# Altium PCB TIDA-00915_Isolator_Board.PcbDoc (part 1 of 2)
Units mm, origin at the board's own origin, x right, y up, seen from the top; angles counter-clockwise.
Board outline 80 x 46 mm, 4 copper layers (Top Layer, L2, L3, Bottom Layer), stack 0.8 mm thick; 132 components, 79 nets, 362 pads, 253 vias.
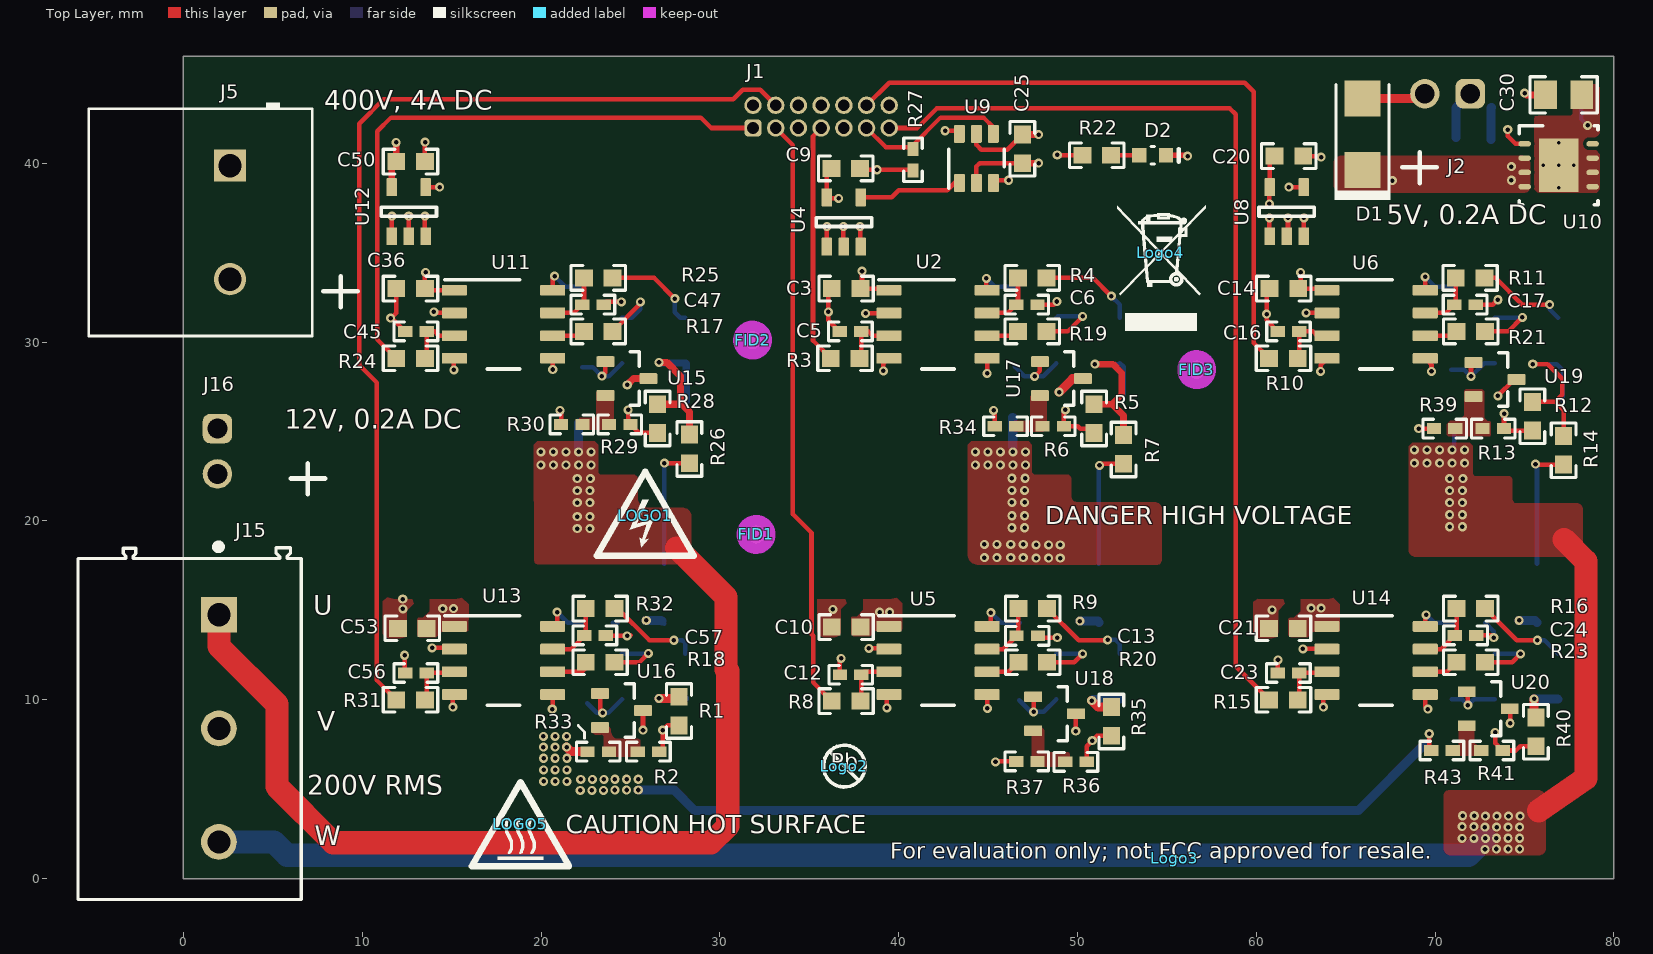
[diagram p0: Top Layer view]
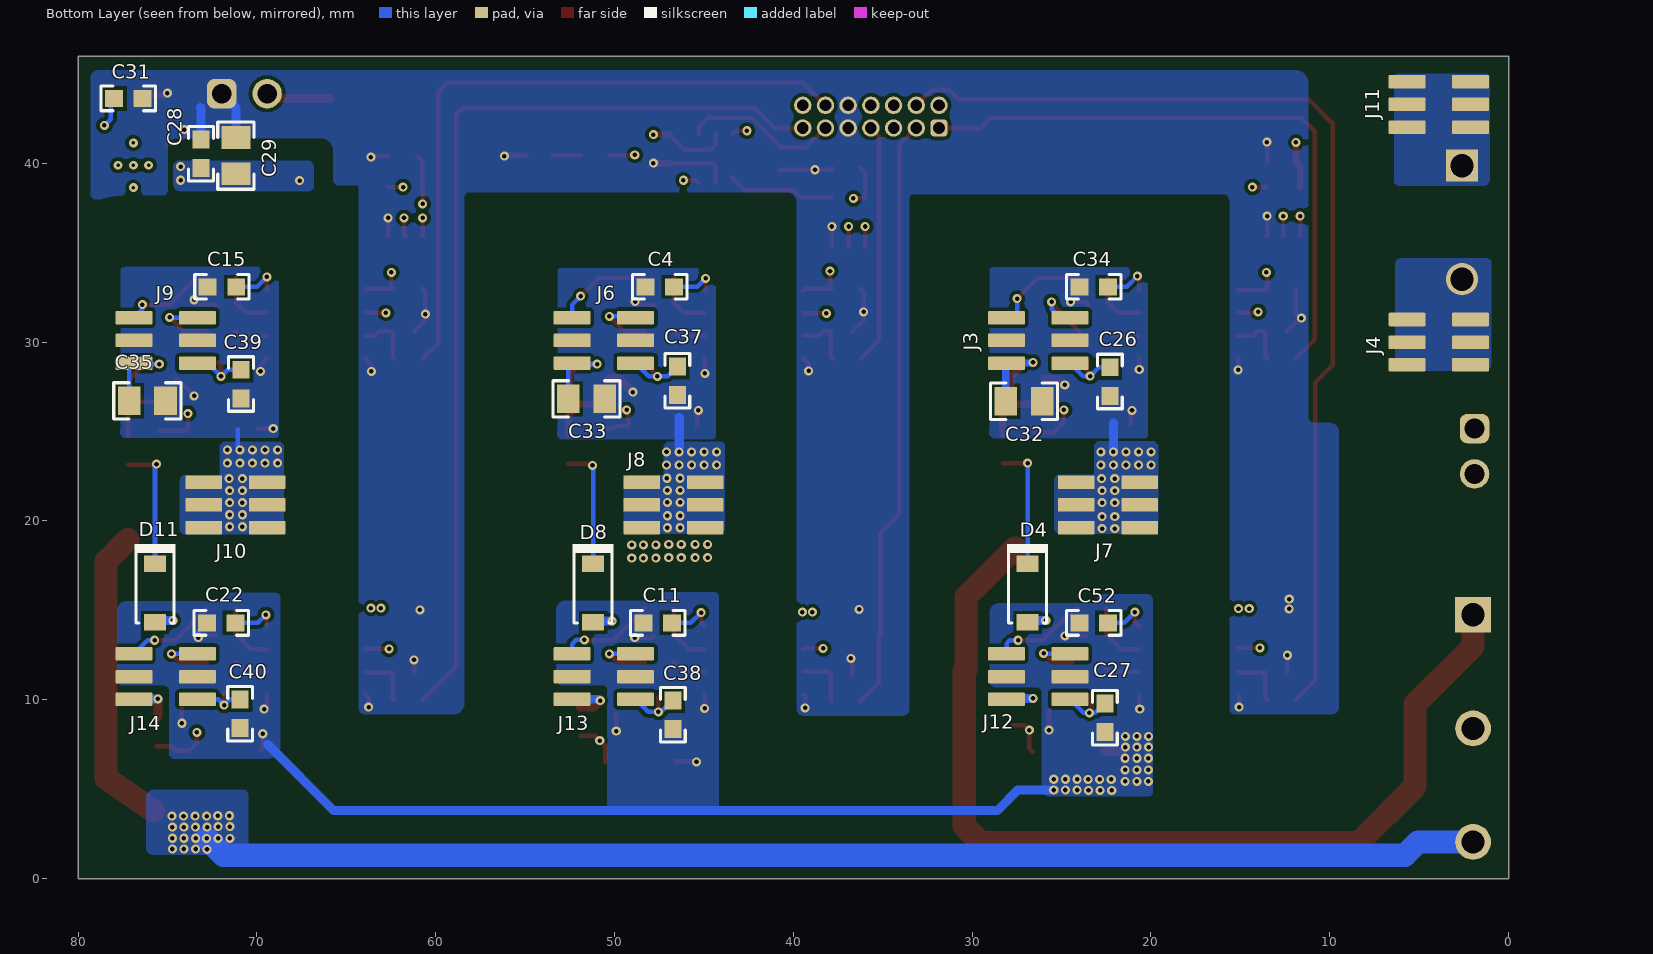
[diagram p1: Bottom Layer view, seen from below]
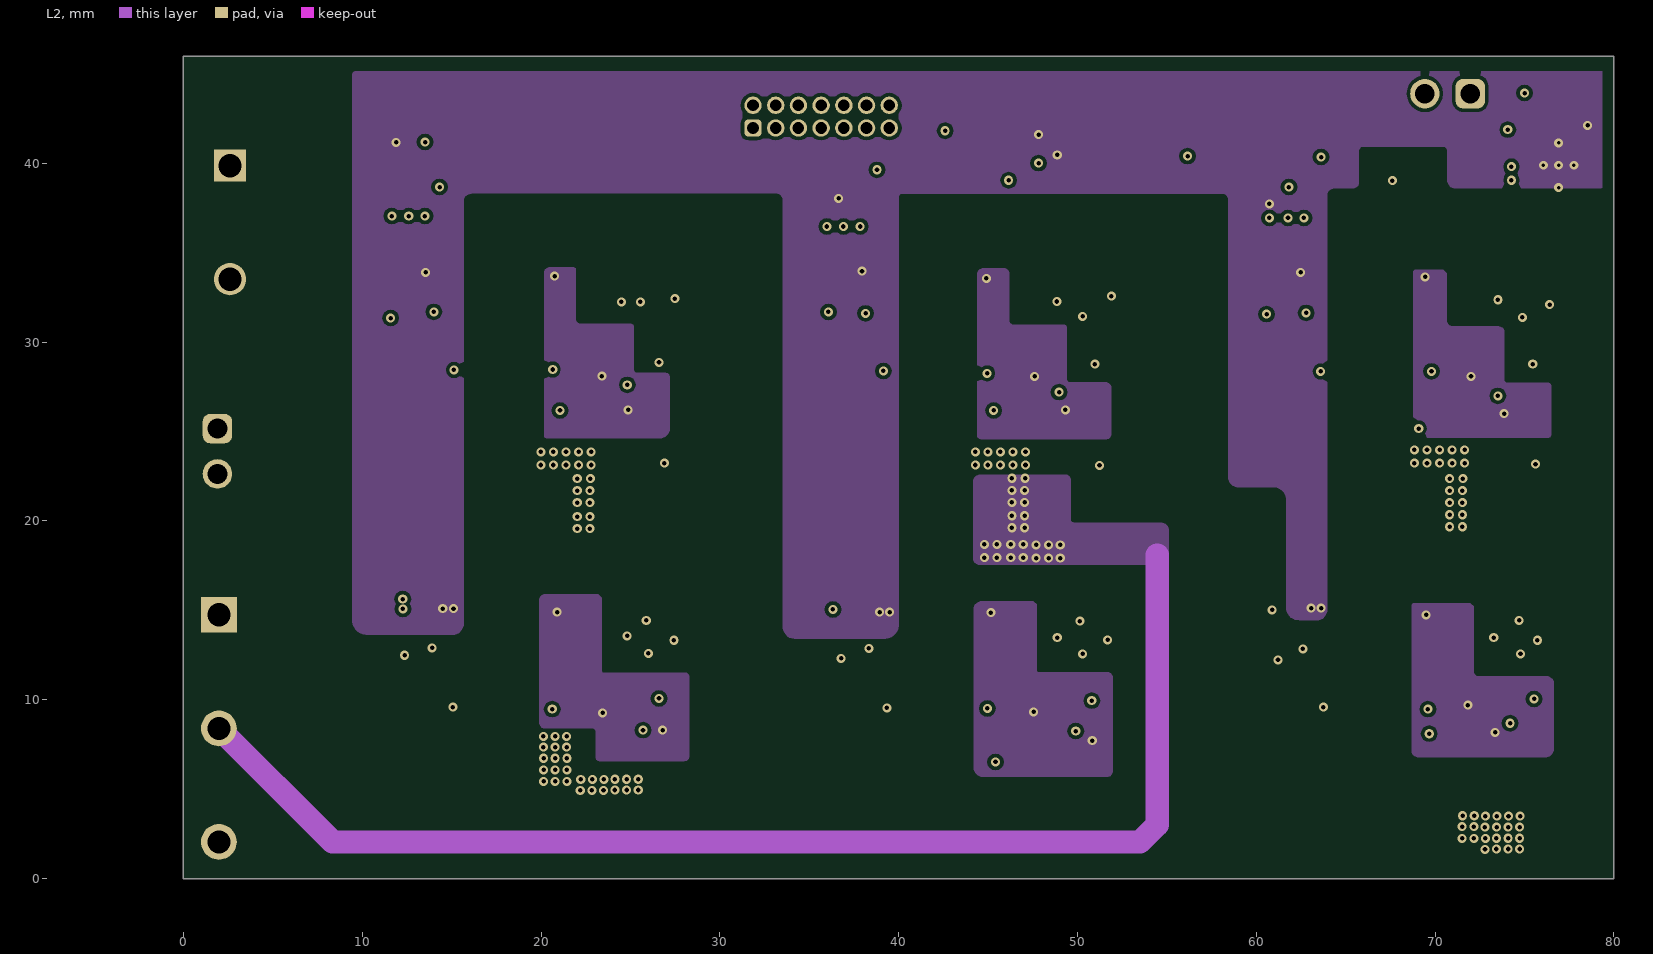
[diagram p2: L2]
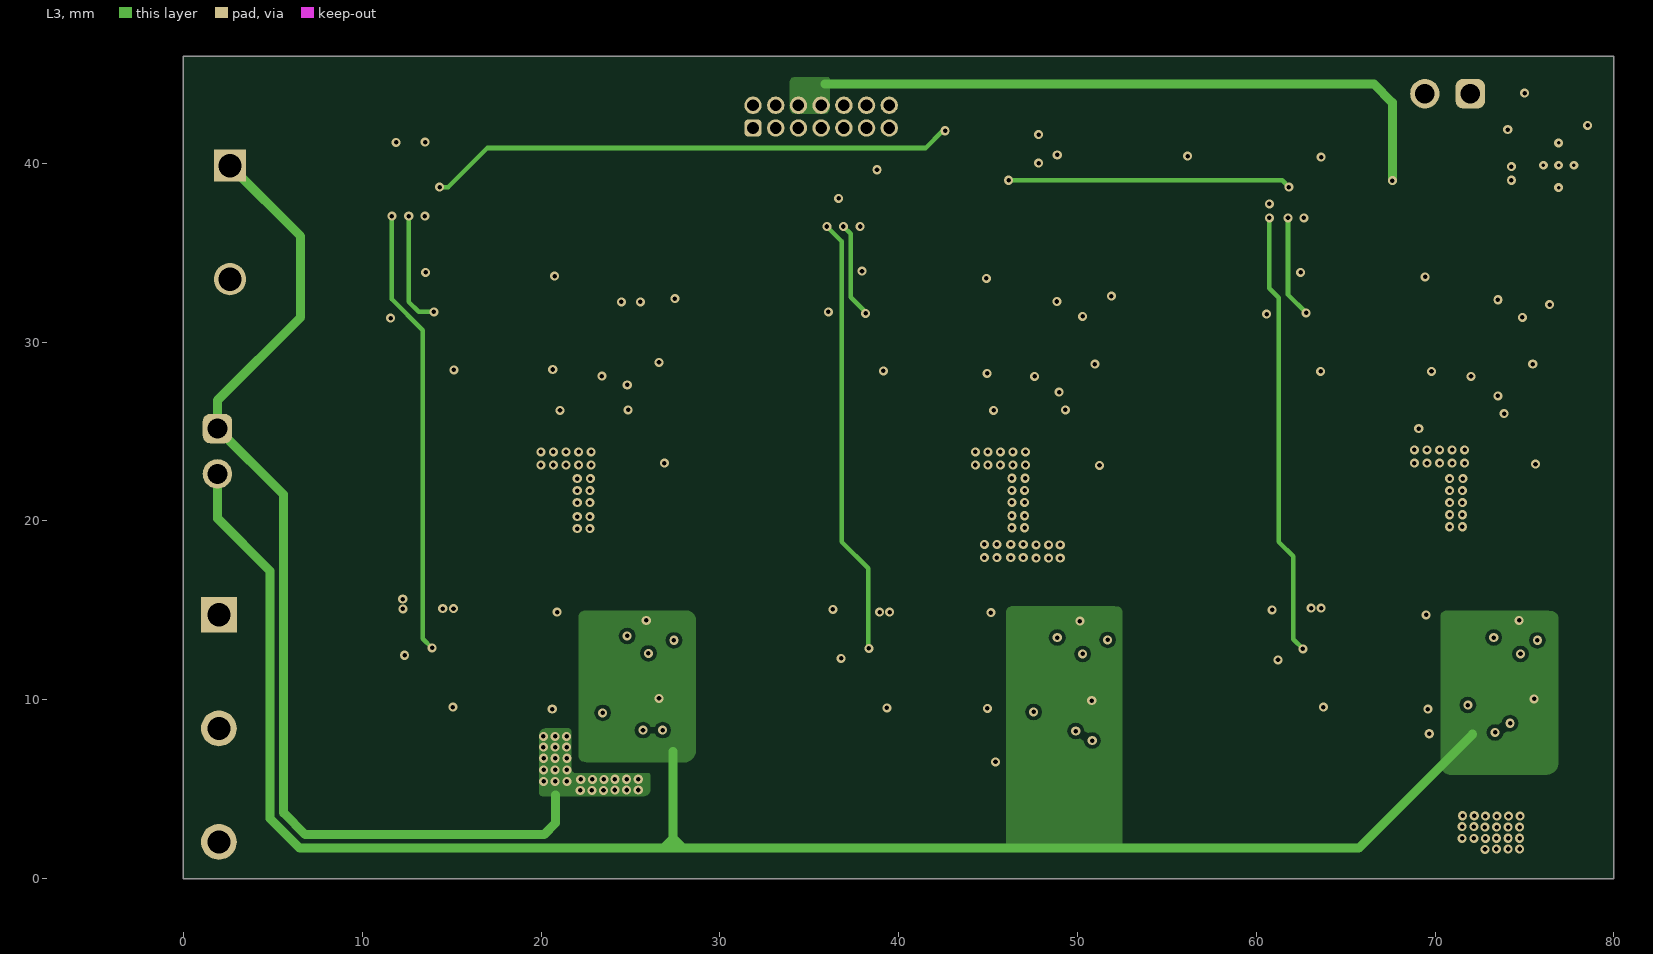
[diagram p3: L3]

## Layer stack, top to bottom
Top Solder: solder mask 0.0102, Solder Resist, Dk 3.5
Top Layer: signal copper 0.07
Dielectric 2: dielectric 0.16, FR-4  High Tg, Dk 4.2
L2: signal copper 0.07
Dielectric1: core 0.2, FR-4  High Tg, Dk 4.8
L3: signal copper 0.07
Dielectric 3: dielectric 0.16, FR-4  High Tg, Dk 4.2
Bottom Layer: signal copper 0.07
Bottom Solder: solder mask 0.0102, Solder Resist, Dk 3.5

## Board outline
0,0 80,0 80,46 0,46

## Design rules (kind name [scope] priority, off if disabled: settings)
AcuteAngle [All] p1: minimum=4.50000000000000E+0001 checktracksonly=FALSE
AssemblyTestPointUsage [All] p1: valid=2
BoardOutlineClearance BoardOutlineClearance_MountingHoles [OnCopper and InComponentClass('Mounting Holes')] p1: gap=1.016 ignorepadtopadclearanceinfootprint=FALSE
BoardOutlineClearance BoardOutlineClearance_Poly [OnCopper and IsPoly] p2: gap=0.635 ignorepadtopadclearanceinfootprint=FALSE
BoardOutlineClearance [OnCopper and Not InComponentClass('Logo') and not InComponentClass('FiducialMark') and not InRegion(1000,500,4000,800) and not InPoly] p3: gap=0.6 ignorepadtopadclearanceinfootprint=FALSE
Clearance "LV Clearance" [InNetClass('LV') vs NOT (InNetClass('LV') OR InComponentClass('FiducialMark'))] p1: gap=4 ignorepadtopadclearanceinfootprint=TRUE except(0: Arc-Hole Track-Hole SMDPad-Hole THPad-Hole Via-Hole Fill-Hole Poly-Hole Region-Hole Text-Hole)
Clearance PhaseU [InNetClass('PhaseU') vs NOT InNetClass('PhaseU')] p2: gap=1.6 ignorepadtopadclearanceinfootprint=FALSE except(0: Arc-Hole Track-Hole SMDPad-Hole THPad-Hole Via-Hole Fill-Hole Poly-Hole Region-Hole Text-Hole)
Clearance PhaseV [InNetClass('PhaseV') vs NOT InNetClass('PhaseV')] p3: gap=1.6 ignorepadtopadclearanceinfootprint=FALSE except(0: Arc-Hole Track-Hole SMDPad-Hole THPad-Hole Via-Hole Fill-Hole Poly-Hole Region-Hole Text-Hole)
Clearance PhaseW [InNetClass('PhaseW') vs NOT InNetClass('PhaseW')] p4: gap=1.6 ignorepadtopadclearanceinfootprint=FALSE except(0: Arc-Hole Track-Hole SMDPad-Hole THPad-Hole Via-Hole Fill-Hole Poly-Hole Region-Hole Text-Hole)
Clearance Clearance_Keepouts [((IsTrack Or IsArc) And Not InPoly) And IsFree and IsKeepOut vs ((IsTrack Or IsArc) And Not InPoly) And IsFree and IsKeepOut] p5: gap=0 ignorepadtopadclearanceinfootprint=FALSE
Clearance Clearance_Poly [InPolygon] p6: gap=0.635 ignorepadtopadclearanceinfootprint=FALSE except(0: Arc-Hole Track-Hole SMDPad-Hole THPad-Hole Via-Hole Fill-Hole Poly-Hole Region-Hole Text-Hole; 0.2: Arc-Fill Arc-Poly Arc-Region Track-Fill Track-Poly Track-Region SMDPad-Fill SMDPad-Poly SMDPad-Region THPad-Fill THPad-Poly THPad-Region Via-Fill Via-Poly Via-Region Fill-Fill Fill-Poly Fill-Region Poly-Poly Poly-Region Region-Region)
Clearance Clearance_FiducialMark [IsKeepOut and InComponentClass('FiducialMark') vs IsPad and InComponentClass('FiducialMark')] p7: gap=0 ignorepadtopadclearanceinfootprint=FALSE
Clearance [All] p8: gap=0.254 ignorepadtopadclearanceinfootprint=FALSE except(0: Arc-Hole Track-Hole SMDPad-Hole THPad-Hole Via-Hole Fill-Hole Poly-Hole Region-Hole Text-Hole)
ComponentClearance ComponentClearance_MountingHoles_FiducialMarks [InComponentClass('Mounting Holes') vs InComponentClass('FiducialMark')] p1: gap=1.27 collisioncheckmode=3 verticalgap=0.254 showdistances=FALSE
ComponentClearance ComponentClearance_Shunt [InComponentClass('Header') vs InComponentClass('Shunt')] p2: gap=0 collisioncheckmode=3 verticalgap=0 showdistances=FALSE
ComponentClearance ComponentClearance_Logo [InComponentClass('Logo')] p3: gap=1.27 collisioncheckmode=3 verticalgap=0.254 showdistances=FALSE
ComponentClearance ComponentClearance_ScrewToNut [(HasFootprint('NY PMS 440 0025 PH')) vs (HasFootprint('Keystone_1902C'))] p4: gap=0.127 collisioncheckmode=3 verticalgap=0.254 showdistances=FALSE
ComponentClearance ComponentClearance_MountingHoles [InComponentClass('Mounting Holes')] p5: gap=6.35 collisioncheckmode=3 verticalgap=2540 showdistances=FALSE
ComponentClearance ComponentClearance_SmallPassives [HasFootprint('0201*') or HasFootprint('0402*') or HasFootprint('0508') or HasFootprint('0603*') or HasFootprint('0612') or HasFootprint('0805*') or HasFootprint('0815*') or HasFootprint('0830*') or HasFootprint('1206*') or HasFootprint('1210*') or HasFootprint('1808*') or HasFootprint('1812*') or HasFootprint('1825*') or HasFootprint('2010*') or HasFootprint('2220*') or HasFootprint('2225*') or HasFootprint('2512*') or HasFootprint('2728*') or HasFootprint('3518*') vs HasFootprint('0201*') or HasFootprint('0402*') or HasFootprint('0508') or HasFootprint('0603*') or HasFootprint('0612') or HasFootprint('0805*') or HasFootprint('0815*') or HasFootprint('0830*') or HasFootprint('1206*') or HasFootprint('1210*') or HasFootprint('1808*') or HasFootprint('1812*') or HasFootprint('1825*') or HasFootprint('2010*') or HasFootprint('2220*') or HasFootprint('2225*') or HasFootprint('2512*') or HasFootprint('2728*') or HasFootprint('3518*')] p6: gap=0.38 collisioncheckmode=3 verticalgap=0.254 showdistances=FALSE
ComponentClearance ComponentClearance_THtoSMT [IsThruComponent vs IsSMTComponent] p7: gap=0.508 collisioncheckmode=3 verticalgap=0.762 showdistances=FALSE
ComponentClearance ComponentClearance_THtoTH [IsThruComponent vs IsThruComponent] p8: gap=0.762 collisioncheckmode=3 verticalgap=0.762 showdistances=FALSE
ComponentClearance [All] p9: gap=0 collisioncheckmode=3 verticalgap=0 showdistances=FALSE
DiffPairsRouting [All] p1: maxlimit=2.54 minlimit=0.254 mostfreqgap=0.254 toplayer_minwidth=0.381 toplayer_maxwidth=0.381 toplayer_prefwidth=0.381 midlayer1_minwidth=0.381 midlayer1_maxwidth=0.381 midlayer1_prefwidth=0.381 midlayer2_minwidth=0.381 midlayer2_maxwidth=0.381 midlayer2_prefwidth=0.381 bottomlayer_minwidth=0.381 bottomlayer_maxwidth=0.381 bottomlayer_prefwidth=0.381 maxuncoupledlength=25.4
FabricationTestPointUsage TestPointUsage [All] p1: valid=2 allowmultiple=FALSE
FabricationTestpoint Testpoint [All] p1: side=3 testpointundercomponent=TRUE minsize=1.016 maxsize=2.54 preferedsize=1.524 minholesize=0 maxholesize=1.016 preferedholesize=0.813 testpointgrid=0.025 allowsidetop=TRUE allowsidebottom=TRUE usegrid=TRUE gridtolerance=0
FanoutControl Fanout_LCC [IsLCC] p1: bgadir=Out bgaviamode=Centered fanoutstyle=Auto fanoutdirection=Alternating viagrid=0.025 // Fanout_LCC (Default Rule)
FanoutControl Fanout_BGA [IsBGA] p2: bgadir=Out bgaviamode=Centered fanoutstyle=Auto fanoutdirection=Alternating viagrid=0.025 // Fanout_BGA (Default Rule)
FanoutControl Fanout_Default [All] p4: bgadir=Out bgaviamode=Centered fanoutstyle=Auto fanoutdirection=Alternating viagrid=0.025 // Fanout_Default (Default Rule)
FanoutControl Fanout_Small [(CompPinCount < 5)] p5: bgadir=Out bgaviamode=Centered fanoutstyle=Auto fanoutdirection=OutThenIn viagrid=0.025 // Fanout_Small (Default Rule)
HoleSize [All] p1: absolutevalues=TRUE maxlimit=6.375 minlimit=0.2 maxpercent=80.000 minpercent=20.000
MinimumAnnularRing MinimumAnnularRing_ThermalPadVias [IsVia and InAnyComponent] p1: minimumring=0.127
MinimumAnnularRing [All] p2: minimumring=0.127
MinimumSolderMaskSliver MinimumSolderMaskSliver_Logo [InComponentClass('Logo') vs InComponentClass('Logo')] p1: minsoldermaskwidth=0.018
MinimumSolderMaskSliver [All] p2: minsoldermaskwidth=0.1
PlaneConnect [All] p1: planeconnectstyle=Relief reliefexpansion=0.254 reliefentries=4 reliefconductorwidth=0.254 reliefairgap=0.254
PolygonConnect [All] p1: connectstyle=Direct reliefconductorwidth=0.254 reliefentries=4 polygonreliefangle="90 Angle" airgapwidth=0.254
RoutingVias ThermalPadVias [IsVia and InAnyComponent] p1: holewidth=0.2 width=0.5 viastyle="Through Hole" minholewidth=0.2 minwidth=0.5 maxholewidth=0.33 maxwidth=0.6
RoutingVias [All] p2: holewidth=0.406 width=0.864 viastyle="Through Hole" minholewidth=0.2 minwidth=0.508 maxholewidth=1.016 maxwidth=1.651
SilkToBoardRegionClearance [Not ((IsComment or IsDesignator) And (Hide <> 'False')) and not InRegion(1000,500,4000,800)] p1:
SilkToSilkClearance SilkToSilkClearance_Pb-FreeLogo [(HasFootprint('Pb-Free_Overlay_Medium') OR HasFootprint('Pb-Free_Overlay_Small')) vs (HasFootprint('Pb-Free_Overlay_Medium') OR HasFootprint('Pb-Free_Overlay_Small'))] p1: silktosilkclearance=0
SilkToSilkClearance [All] p2: silktosilkclearance=0.102
SilkToSolderMaskClearance SilkToComponentPadClearance [(IsPad or IsFill or IsRegion) and InAnycomponent] p1: minsilkscreentomaskgap=0.127 clearancetoexposedcopper=TRUE
SilkToSolderMaskClearance "Silk to Solder Mask Opening" [All] p2: minsilkscreentomaskgap=0.102 clearancetoexposedcopper=FALSE
SolderMaskExpansion [All] p1: expansion=0.05
Width [All] p1: maxlimit=2.54 minlimit=0.152 preferedwidth=0.254 checkconnectedcopper=TRUE
15 further rules are at their usual default settings.

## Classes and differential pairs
net class LV: 3V3 5V Bot_FET_U Bot_FET_V Bot_FET_W FLT_L_U FLT_L_V FLT_L_W FLT_T_U FLT_T_V FLT_T_W "GaN Fault" "GaN Fault U" "GaN Fault V" "GaN Fault W" GND NC1 NC2 NC3 NC4 NetC5_1 NetC12_1 NetC16_1 NetC23_1 NetC45_1 NetC56_1 NetD1_2 NetD2_1 Top_FET_U Top_FET_V Top_FET_W
component class Phase_U: C26 C27 C32 C34 C36 C45 C47 C52 C53 C56 C57 D4 J3 J4 J5 J7 J11 J12 J15 J16 R1 R2 R17 R18 R24 R25 R26 R28 R29 R30 R31 R32 R33 U11 U13 U15 U16
component class MCU_Interface: C9 C20 C25 C28 C29 C30 C31 C50 D1 D2 J1 J2 R22 R27 U4 U8 U9 U10 U12
component class Phase_W: C14 C15 C16 C17 C21 C22 C23 C24 C35 C39 C40 D11 J9 J10 J14 R10 R11 R12 R13 R14 R15 R16 R21 R23 R39 R40 R41 R43 U6 U14 U19 U20
component class Phase_V: C3 C4 C5 C6 C10 C11 C12 C13 C33 C37 C38 D8 J6 J8 J13 R3 R4 R5 R6 R7 R8 R9 R19 R20 R34 R35 R36 R37 U2 U5 U17 U18
component class Header: J1
component class EVM_Hardware: FID1 FID2 FID3 LOGO1 Logo2 Logo3 Logo4 LOGO5
component class FiducialMark: FID1 FID2 FID3
net class PhaseU: 5V_H_U 12V_T_U FAULT_H_U IN_H_U NetC47_1 NetD4_1 NetR17_1 NetR29_1 PHASEU
net class PhaseV: 5V_H_V 12V_T_V FAULT_H_V IN_H_V NetC6_1 NetD8_1 NetR6_1 NetR19_1 PHASEV
net class PhaseW: 5V_H_W 12V_T_W FAULT_H_W IN_H_W NetC17_1 NetD11_1 NetR13_1 NetR21_1 PHASEW

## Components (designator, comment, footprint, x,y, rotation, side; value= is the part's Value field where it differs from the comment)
C3 "06035C104KAT2A" 0603 37.059,33 r0 top value=0.1uF
C4 "06035C104KAT2A" 0603 47.473,33.1 r0 bottom value=0.1uF
C5 "C1005C0G1H680J050BA" 0402 37.3,30.6 r180 top value=68pF
C6 "C1005C0G1H680J050BA" 0402 47.168,32.1 r0 top value=68pF
C9 "06035C104KAT2A" 0603 37.033,39.719 r0 top value=0.1uF
C10 "06035C104KAT2A" 0603 37.059,14.065 r0 top value=0.1uF
C11 "06035C104KAT2A" 0603 47.574,14.3 r0 bottom value=0.1uF
C12 "C1005C0G1H680J050BA" 0402 37.313,11.398 r180 top value=68pF
C13 "C1005C0G1H680J050BA" 0402 47.193,13.575 r0 top value=68pF
C14 "06035C104KAT2A" 0603 61.544,33 r0 top value=0.1uF
C15 "06035C104KAT2A" 0603 71.958,33.1 r0 bottom value=0.1uF
C16 "C1005C0G1H680J050BA" 0402 61.8,30.6 r180 top value=68pF
C17 "C1005C0G1H680J050BA" 0402 71.679,32.1 r0 top value=68pF
C20 "06035C104KAT2A" 0603 61.824,40.405 r0 top value=0.1uF
C21 "06035C104KAT2A" 0603 61.519,14 r0 top value=0.1uF
C22 "06035C104KAT2A" 0603 72,14.3 r0 bottom value=0.1uF
C23 "C1005C0G1H680J050BA" 0402 61.798,11.5 r180 top value=68pF
C24 "C1005C0G1H680J050BA" 0402 71.704,13.6 r0 top value=68pF
C25 "C1608X7R1H104K" 0603 46.914,40.811 r270 top value=0.1uF
C26 "06035C104KAT2A" 0603 22.3,27.8 r270 bottom value=0.1uF
C27 "06035C104KAT2A" 0603 22.575,9 r270 bottom value=0.1uF
C28 "06035C104KAT2A" 0603 73.127,40.538 r90 bottom value=0.1uF
C29 "C2012X7R1V475K125AC" 0805_HV 71.171,40.43 r270 bottom value=4.7uF
C30 "C2012X7R1V475K125AC" 0805_HV 77.191,43.834 r0 top value=4.7uF
C31 "06035C104KAT2A" 0603 77.191,43.631 r180 bottom value=0.1uF
C32 "C2012X7R1V475K125AC" 0805_HV 27.1,26.7 r180 bottom value=4.7uF
C33 "C2012X7R1V475K125AC" 0805_HV 51.569,26.827 r180 bottom value=4.7uF
C34 "06035C104KAT2A" 0603 23.2,33.1 r0 bottom value=0.1uF
C35 "C2012X7R1V475K125AC" 0805_HV 76.131,26.721 r180 bottom value=4.7uF
C36 "06035C104KAT2A" 0603 12.7,33 r0 top value=0.1uF
C37 "06035C104KAT2A" 0603 46.482,27.838 r270 bottom value=0.1uF
C38 "06035C104KAT2A" 0603 46.736,9.169 r270 bottom value=0.1uF
C39 "06035C104KAT2A" 0603 70.891,27.661 r270 bottom value=0.1uF
C40 "06035C104KAT2A" 0603 70.942,9.22 r270 bottom value=0.1uF
C45 "C1005C0G1H680J050BA" 0402 13,30.6 r180 top value=68pF
C47 "C1005C0G1H680J050BA" 0402 22.9,32.1 r0 top value=68pF
C50 "06035C104KAT2A" 0603 12.7,40.1 r0 top value=0.1uF
C52 "06035C104KAT2A" 0603 23.2,14.3 r0 bottom value=0.1uF
C53 "06035C104KAT2A" 0603 12.8,14 r0 top value=0.1uF
C56 "C1005C0G1H680J050BA" 0402 13,11.5 r180 top value=68pF
C57 "C1005C0G1H680J050BA" 0402 23.012,13.6 r0 top value=68pF
D1 "B1100-13-F" SMA 65.938,41.624 r90 top value=100V
D2 "LG L29K-G2J1-24-Z" "LG L29K_GREEN" 54.204,40.456 r0 top value=Green
D4 "UFM15PL-TP" SOD-123FL 26.899,15.97 r270 bottom value=600V
D8 "UFM15PL-TP" SOD-123FL 51.2,15.97 r270 bottom value=600V
D11 "UFM15PL-TP" SOD-123FL 75.7,15.97 r270 bottom value=600V
FID1 "Fiducial" Fiducial10-20 32.029,19.247 r0 top
FID2 "Fiducial" Fiducial10-20 31.826,30.118 r0 top
FID3 "Fiducial" Fiducial10-20 56.667,28.467 r0 top
J1 "20021111-00014T4LF" FCI_20021111-00014T4LF 35.662,42.615 r90 top
J2 "1725656" CONN_1725656_1 70.7,43.9 r180 top
J3 "20021321-00006C4LF" FCI_20021321-00006XXLF 26.3,30.1 r180 bottom locked
J4 "20021321-00006C4LF" FCI_20021321-00006XXLF 3.9,30 r180 bottom locked
J5 "1714955" Phoenix_1714955 2.6,36.7 r270 top
J6 "20021321-00006C4LF" FCI_20021321-00006XXLF 50.6,30.1 r180 bottom locked
J7 "20021321-00006C4LF" FCI_20021321-00006XXLF 22.4,20.9 r180 bottom locked
J8 "20021321-00006C4LF" FCI_20021321-00006XXLF 46.7,20.9 r180 bottom locked
J9 "20021321-00006C4LF" FCI_20021321-00006XXLF 75.1,30.1 r180 bottom locked
J10 "20021321-00006C4LF" FCI_20021321-00006XXLF 71.2,20.9 r180 bottom locked
J11 "20021321-00006C4LF" FCI_20021321-00006XXLF 3.9,43.3 r180 bottom locked
J12 "20021321-00006C4LF" FCI_20021321-00006XXLF 26.3,11.3 r180 bottom locked
J13 "20021321-00006C4LF" FCI_20021321-00006XXLF 50.6,11.3 r180 bottom locked
J14 "20021321-00006C4LF" FCI_20021321-00006XXLF 75.1,11.3 r180 bottom locked
J15 "1714968" Phoenix_1714968 1.981,8.4 r270 top
J16 "1725656" CONN_1725656_1 1.9,23.9 r270 top
LOGO1 "DANGER HIGH VOLTAGE" IEC_HighVoltage_Small 25.832,20.295 r0 top
Logo2 "Pb-Free Symbol" Pb-Free_Overlay_Small 36.957,6.293 r0 top
Logo3 "FCC disclaimer" FCC_disclaimer 55.448,1.143 r0 top
Logo4 "WEEE logo" WEEE_Minimum 54.661,35.001 r0 top
LOGO5 "CAUTION HOT SURFACE" IEC_HotSurface_Small 18.847,3.048 r0 top
R1 "RC0603FR-071KL" 0603 27.711,9.373 r270 top value=1.00k
R2 "RC0402FR-0710KL" 0402 26,7.1 r0 top value=10.0k
R3 "RC0603FR-0749R9L" 0603 37,29.1 r0 top value=49.9
R4 "RC0603FR-0749R9L" 0603 47.473,33.6 r0 top value=49.9
R5 "RC0603FR-071KL" 0603 50.927,25.73 r270 top value=1.00k
R6 "RC0402FR-0710KL" 0402 48.641,25.298 r0 top value=10.0k
R7 "CRCW06033R30JNEA" 0603 52.578,24.003 r90 top value=3.3
R8 "RC0603FR-0749R9L" 0603 37.059,9.925 r0 top value=49.9
R9 "RC0603FR-0749R9L" 0603 47.498,15.1 r0 top value=49.9
R10 "RC0603FR-0749R9L" 0603 61.519,29.1 r0 top value=49.9
R11 "RC0603FR-0749R9L" 0603 71.958,33.6 r0 top value=49.9
R12 "RC0603FR-071KL" 0603 75.438,25.857 r270 top value=1.00k
R13 "RC0402FR-0710KL" 0402 73.254,25.171 r0 top value=10.0k
R14 "CRCW06033R30JNEA" 0603 77.191,23.952 r90 top value=3.3
R15 "RC0603FR-0749R9L" 0603 61.519,10 r0 top value=49.9
R16 "RC0603FR-0749R9L" 0603 72,15.1 r0 top value=49.9
R17 "RC0603FR-0715RL" 0603 23.2,30.6 r0 top value=15.0
R18 "RC0603FR-0715RL" 0603 23.3,12.1 r0 top value=15.0
R19 "RC0603FR-0715RL" 0603 47.473,30.6 r0 top value=15.0
R20 "RC0603FR-0715RL" 0603 47.5,12.1 r0 top value=15.0
R21 "RC0603FR-0715RL" 0603 72,30.6 r0 top value=15.0
R22 "RT0603BRB071KL" 0603 51.079,40.456 r180 top value=1.00k
R23 "RC0603FR-0715RL" 0603 72,12.1 r0 top value=15.0
R24 "RC0603FR-0749R9L" 0603 12.7,29.1 r0 top value=49.9
R25 "RC0603FR-0749R9L" 0603 23.2,33.6 r0 top value=49.9
R26 "CRCW06033R30JNEA" 0603 28.296,24.028 r90 top value=3.3
R27 "RC0402FR-074K7L" 0402 40.8,40.2 r90 top value=4.70k
R28 "RC0603FR-071KL" 0603 26.518,25.73 r270 top value=1.00k
R29 "RC0402FR-0710KL" 0402 24.4,25.4 r0 top value=10.0k
R30 "RC0402FR-0710KL" 0402 21.717,25.4 r0 top value=10.0k
R31 "RC0603FR-0749R9L" 0603 12.7,10 r0 top value=49.9
R32 "RC0603FR-0749R9L" 0603 23.3,15.1 r0 top value=49.9
R33 "RC0402FR-0710KL" 0402 23.2,7.1 r0 top value=10.0k
R34 "RC0402FR-0710KL" 0402 45.974,25.298 r0 top value=10.0k
R35 "RC0603FR-071KL" 0603 51.892,8.788 r270 top value=1.00k
R36 "RC0402FR-0710KL" 0402 49.911,6.528 r0 top value=10.0k
R37 "RC0402FR-0710KL" 0402 47.168,6.553 r0 top value=10.0k
R39 "RC0402FR-0710KL" 0402 70.536,25.171 r0 top value=10.0k
R40 "RC0603FR-071KL" 0603 75.641,8.204 r270 top value=1.00k
R41 "RC0402FR-0710KL" 0402 73.177,7.163 r0 top value=10.0k
R43 "RC0402FR-0710KL" 0402 70.383,7.163 r0 top value=10.0k
U2 "ISO7721FDR" D0008B_HV 42.2,31 r0 top locked
U4 "SN74AHC1G08DBVR" DBV0005A_N 36.932,36.722 r90 top
U5 "ISO7721FDR" D0008B_HV 42.2,12.2 r0 top locked
U6 "ISO7721FDR" D0008B_HV 66.7,31 r0 top locked
U8 "SN74AHC1G08DBVR" DBV0005A_N 61.7,37.3 r90 top
U9 "SN74LVC1G11DBVR" DBV0006A_N 44.348,40.278 r90 top
U10 "TLV1117-33CDRJR" DRJ0008A 76.911,39.897 r0 top
U11 "ISO7721FDR" D0008B_HV 17.9,31 r0 top locked
U12 "SN74AHC1G08DBVR" DBV0005A_N 12.6,37.3 r90 top
U13 "ISO7721FDR" D0008B_HV 17.9,12.2 r0 top locked
U14 "ISO7721FDR" D0008B_HV 66.7,12.2 r0 top locked
U15 "TL431ACDBZT" DBZ0003A_N 24.8,27.965 r0 top
U16 "TL431ACDBZT" DBZ0003A_N 24.5,9.4 r0 top
U17 "TL431ACDBZT" DBZ0003A_N 49.1,27.965 r0 top
U18 "TL431ACDBZT" DBZ0003A_N 48.717,9.22 r0 top
U19 "TL431ACDBZT" DBZ0003A_N 73.355,27.915 r0 top
U20 "TL431ACDBZT" DBZ0003A_N 72.974,9.5 r0 top
ZZ1 "This Assembly Note is for PCB labels only" AssemblyNoteLabel 3.27,123.698 r0 top
ZZ2 "These assemblies are ESD sensitive, ESD precautions shall be observed." AssemblyNote 3.397,110.744 r0 top
ZZ3 "These assemblies must be clean and free from flux and all contaminants. Use of no clean flux is not acceptable." AssemblyNote 3.397,115.24 r0 top
ZZ4 "These assemblies must comply with workmanship standards IPC-A-610 Class 2, unless otherwise specified." AssemblyNote 3.397,119.736 r0 top

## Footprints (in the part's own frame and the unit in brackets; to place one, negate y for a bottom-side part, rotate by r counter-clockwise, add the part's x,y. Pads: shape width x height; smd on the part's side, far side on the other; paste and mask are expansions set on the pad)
0402 [mm] "0402 from SM-752 data"
  rect 0.8x0.6 smd: 1(-0.6,0) 2(0.6,0)
  silkscreen extent -1.22,-0.52 1.22,0.52, body extent -0.55,-0.3 0.55,0.3, height 0.6
0603 [mm] "0603 from SM-752 data"
  rect 1x0.95 smd: 1(-0.8,0) 2(0.8,0)
  silkscreen extent -1.52,-0.69 1.52,0.69, body extent -0.87,-0.47 0.87,0.47, height 1
0805_HV [mil] "0805 with 30mil clearance between pads"
  rect 50x63 smd: 1(-40,0) 2(40,0)
  silkscreen extent -74,-40 74,40, body extent -43,-29 43,29, height 57
AssemblyNote [mm] "Assembly Note"
AssemblyNoteLabel [mm] "Assembly Note for PCB Labels"
CONN_1725656_1 [mm] "Terminal Block, 2.54 mm, 2 Pos, TH"
  rrect50% 1.65x1.65 hole 1.1: 1(-1.27,0)
  round 1.65 hole 1.1: 2(1.27,0)
  body extent -2.77,-3.1 2.77,3.1, height 8.5
D0008B_HV [mm] "SOIC, 8-Leads, Body 4.9x3.9mm, Pitch 1.27mm, HV / Isolation option"
  rrect17% 1.4x0.6 smd: 1(-2.75,1.905) 2(-2.75,0.635) 3(-2.75,-0.635) 4(-2.75,-1.905) 5(2.75,-1.905) 6(2.75,-0.635) 7(2.75,0.635) 8(2.75,1.905)
  silkscreen extent -3.3,-2.5 0.9,2.5, body extent -3,-2.45 3,2.45, height 1.63
DBV0005A_N [mm] "SOT23, 5-Leads, Body 2.9x1.6mm, Pitch 0.95mm, Lead Span 2.8mm, IPC Medium Density"
  rrect17% 1x0.6 smd: 1(-1.375,0.95) 2(-1.375,0) 3(-1.375,-0.95) 4(1.375,-0.95) 5(1.375,0.95)
  silkscreen extent -0.25,-1.55 0.25,1.55, body extent -1.42,-1.46 1.42,1.46, height 1.09
DBV0006A_N [mm] "SOT23, 6-Leads, Body 2.9x1.6mm, Pitch 0.95mm, Lead Span 2.8mm, IPC Medium Density"
  rrect17% 1x0.6 smd: 1(-1.375,0.95) 2(-1.375,0) 3(-1.375,-0.95) 4(1.375,-0.95) 5(1.375,0) 6(1.375,0.95)
  silkscreen extent -1.68,-1.55 0.5,1.55, body extent -1.42,-1.46 1.42,1.46, height 1.12
DBZ0003A_N [mm] "SOT23, 3-Leads, Body 2.9x1.3mm, Pitch 0.95mm, Lead Span 2.4mm, IPC Medium Density"
  rrect17% 1x0.6 smd: 1(-1.2,0.95) 2(-1.2,-0.95) 3(1.2,0)
  silkscreen extent 0.2,-1.5 0.7,1.5, body extent -1.26,-1.46 1.26,1.46, height 0.98
DRJ0008A [mm] "SON, 8-Leads, Body 4x4mm, Pitch 0.8mm, Thermal Pad 3x2.2mm, TI Recommended"
  oval 0.7x0.3 smd: 1(-1.9,1.2) 2(-1.9,0.4) 3(-1.9,-0.4) 4(-1.9,-1.2) 5(1.9,-1.2) 6(1.9,-0.4) 7(1.9,0.4) 8(1.9,1.2)
  rect 2.2x3 smd paste-1.1: 9(0,0)
  silkscreen extent -2.2,-2.2 2.2,2.2, body extent -2.05,-2.05 2.05,2.05, height 0.81
FCC_disclaimer [mm]
FCI_20021111-00014T4LF [mm] "Header, 1.27mm, 7x2, TH"
  rrect50% 0.975x0.975 hole 0.65: 1(-0.635,3.81)
  round 0.975 hole 0.65: 2(0.635,3.81) 3(-0.635,2.54) 4(0.635,2.54) 5(-0.635,1.27) 6(0.635,1.27) 7(-0.635,0) 8(0.635,0) 9(-0.635,-1.27) 10(0.635,-1.27) 11(-0.635,-2.54) 12(0.635,-2.54) 13(-0.635,-3.81) 14(0.635,-3.81)
  body extent -1.7,-4.44 1.7,4.45, height 5.5
FCI_20021321-00006XXLF [mm] "Receptacle, 1.27mm, 3x2, SMT"
  rrect13% 2.05x0.76 smd: 1(-1.775,1.27) 2(1.775,1.27) 3(-1.775,0) 4(1.775,0) 5(-1.775,-1.27) 6(1.775,-1.27)
  body extent -2.25,-2.14 2.25,2.13, height 4.5
Fiducial10-20 [mm]
  round 1 smd mask+0.5: 1(0,0)
  Top Layer keep-out circle w1.178: c0,0 r0.5
IEC_HighVoltage_Small [mm]
  silkscreen extent -2.72,-2.24 2.72,2.47
IEC_HotSurface_Small [mm]
  silkscreen extent -2.72,-2.36 2.72,2.35
"LG L29K_GREEN" [mm] "OSRAM"
  rect 0.8x0.8 smd paste-0.4: 1(-0.75,0) 2(0.75,0)
  silkscreen extent -0.1,-0.5 1.45,0.5, body extent -0.9,-0.45 0.9,0.45, height 0.67
Pb-Free_Overlay_Small [mm]
  silkscreen extent -1.16,-1.17 1.17,1.17
Phoenix_1714955 [mm] "Terminal Block, 2x1, 6.35mm, TH"
  rect 1.8x1.8 hole 1.3: 1(-3.175,0)
  round 1.8 hole 1.3: 2(3.175,0)
  silkscreen extent -6.7,-7.9 6.35,4.6, body extent -6.92,-7.9 6.35,4.6, height 21.5
Phoenix_1714968 [mm] "Phoenix"
  rect 2x2 hole 1.3: 1(-6.35,0)
  round 2 hole 1.3: 2(0,0) 3(6.35,0)
  silkscreen extent -10.34,-7.88 9.57,4.6, body extent -10.06,-7.9 9.56,4.6, height 21.5
SMA [mm] "Molded Diode, 2-Leads, Body 4.3x2.6mm, IPC Medium Density, based on OnSemi component dimensions and land pattern"
  rect 2x2 smd: 1(-2,0) 2(2,0)
  silkscreen extent -3.66,-1.57 2.79,1.57, body extent -2.6,-1.3 2.6,1.3, height 2.42
SOD-123FL [mm] "Copied from SOD-123"
  rect 0.915x1.22 smd: 1(-1.637,0) 2(1.637,0)
  silkscreen extent -2.74,-1.16 1.68,1.16, body extent -1.9,-0.9 1.9,0.9, height 1
WEEE_Minimum [mm] "WEEElie bin"
  silkscreen extent -2.42,-4.38 2.52,2.65

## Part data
C3 C4 C9 C10 C11 C14 C15 C20 C21 C22 C26 C27 C28 C31 C34 C36 C37 C38 C39 C40 C50 C52 C53: library part CMP-0006802-4, "CAP, CERM, 0.1 uF, 50 V, +/- 10%, X7R, 0603", Cap_Case=0603, Manufacturer=AVX, Supplier Part Number 1=478-5052-1-ND, TempCo=X7R, Tolerance_%=10%, Value1=Unknown, Value2=50V, ValueDisplayed=0.1uF
C5 C6 C12 C13 C16 C17 C23 C24 C45 C47 C56 C57: library part CMP-0006251-2, "CAP, CERM, 68 pF, 50 V, +/- 5%, C0G/NP0, 0402", Cap_Case=0402, Manufacturer=TDK, Supplier Part Number 1=445-1245-1-ND, TempCo=C0G/NP0, Tolerance_%=5%, Value1=Unknown, Value2=50V, ValueDisplayed=68pF
C25: "CAP, CERM, 0.1 µF, 50 V, +/- 10%, X7R, 0603", Cap_Case=0603, Manufacturer=TDK, Supplier Part Number 1=445-1314-1-ND, TempCo=X7R, Tolerance_%=10, Value1="0.017 ohm", Value2=50V, ValueDisplayed=0.1µF
C29 C30 C32 C33 C35: library part CMP-0007885-2, "CAP, CERM, 4.7 uF, 35 V, +/- 10%, X7R, 0805", Cap_Case=0805, Manufacturer=TDK, Supplier Part Number 1=445-7555-1-ND, TempCo=X7R, Tolerance_%=10%, Value1="0.002346 ohm", Value2=35V, ValueDisplayed=4.7uF
D1: library part CMP-0028371-2, "Diode, Schottky, 100 V, 1 A, SMA", Manufacturer="Diodes Inc.", Value1=1A, Value2=0.79V
D2: library part CMP-0002874-2, "LED, Green, SMD", Color=green, Manufacturer=OSRAM, Value1=W, Value2=1.7V
D4 D8 D11: library part CMP-0029148-2, "Diode, Ultrafast, 600 V, 1 A, SOD-123FL", Manufacturer="Micro Commercial Components", Value1=1A, Value2=1.7V
FID1 FID2 FID3: library part CMP-0077181-1, "Fiducial mark.  There is nothing to buy or mount.", Manufacturer=N/A
J1: library part CMP-0081712-1, "Header, 1.27mm, 7x2, Gold with Tin tail, TH", Color=Black, Manufacturer=FCI, Supplier Part Number 1=609-3714-ND
J2 J16: library part CMP-0055479-2, "Terminal Block, 100mil, 2x1, 6A, 63V, TH", Manufacturer="Phoenix Contact", Supplier Part Number 1=71C4107
J3 J4 J6 J7 J8 J9 J10 J11 J12 J13 J14: library part CMP-0086011-1, "Receptacle, 1.27mm, 3x2, Gold, SMT", Color=Black, Manufacturer=FCI
J5: library part CMP-0055505-1, "Terminal Block, 2x1, 6.35mm, Green, TH", Color=Green, Manufacturer="Phoenix Contact", Supplier Part Number 1=277-1269-ND
J15: library part CMP-0055483-1, "Terminal Block, 3x1, 6.35 mm, TH", Manufacturer="Phoenix Contact", Supplier Part Number 1=277-1270-ND
LOGO1: library part CMP-0074835-1, "IEC 61010-1 High Voltage Warning"
Logo2: library part CMP-0074839-1
Logo3: library part CMP-0074847-1, "FCC_disclaimer"
Logo4: library part CMP-0074769-1
LOGO5: library part CMP-0074837-1, "IEC 61010-1 Hot Surface Warning"
R1 R5 R12 R28 R35 R40: library part CMP-0022895-5, "RES, 1.00 k, 1%, 0.1 W, 0603", Manufacturer=Yageo, Power_W=100mW, Supplier Part Number 1=311-1.00KHRCT-ND, TempCo="100 ppm/C", Tolerance_%=1%, Value2=0.1W, Value_Code=1k00, ValueDisplayed=1.00k
R2 R6 R13 R29 R30 R33 R34 R36 R37 R39 R41 R43: library part CMP-0078669-1, "RES, 10.0 k, 1%, 0.063 W, 0402", Manufacturer="Yageo America", Power_W=63mW, Supplier Part Number 1=311-10.0KLRCT-ND, TempCo="100 ppm/C", Tolerance_%=1%, Value2=0.063W, Value_Code=10k0, ValueDisplayed=10.0k
R3 R4 R8 R9 R10 R11 R15 R16 R24 R25 R31 R32: library part CMP-0023143-5, "RES, 49.9, 1%, 0.1 W, 0603", Manufacturer=Yageo, Power_W=100mW, Supplier Part Number 1=311-49.9HRCT-ND, TempCo="100 ppm/C", Tolerance_%=1%, Value2=0.1W, Value_Code=49R9, ValueDisplayed=49.9
R7 R14 R26: library part CMP-0025805-4, "RES, 3.3, 5%, 0.1 W, AEC-Q200 Grade 0, 0603", Manufacturer=Vishay-Dale, Power_W=100mW, Supplier Part Number 1=541-3.3GCT-ND, TempCo="200 ppm/C", Tolerance_%=5%, Value2=0.1W, Value_Code=3R30, ValueDisplayed=3.3
R17 R18 R19 R20 R21 R23: library part CMP-0022819-4, "RES, 15.0, 1%, 0.1 W, 0603", Manufacturer=Yageo, Power_W=100mW, Supplier Part Number 1=311-15.0HRCT-ND, TempCo="100 ppm/C", Tolerance_%=1%, Value2=0.1W, Value_Code=15R0, ValueDisplayed=15.0
R22: library part CMP-0023629-3, "RES, 1.00 k, 0.1%, 0.1 W, 0603", Manufacturer="Yageo America", Power_W=100mW, Supplier Part Number 1=YAG2179CT-ND, TempCo="10 ppm/C", Tolerance_%=0.1%, Value2=0.1W, Value_Code=1k00, ValueDisplayed=1.00k
R27: library part CMP-0026739-1, "RES, 4.70 k, 1%, 0.0625 W, 0402", Manufacturer="Yageo America", Power_W=62.5mW, Supplier Part Number 1=311-4.7KLRCT-ND, TempCo="100 ppm/C", Tolerance_%=1%, Value2=0.0625W, Value_Code=4k70, ValueDisplayed=4.70k
U2 U5 U6 U11 U13 U14: library part CMP-0085673-1, "High Speed, Robust EMC Reinforced Dual-Channel Digital Isolator, D0008B (SOIC-8)", Alternate Manufacturer="Texas Instruments", Alternate PartNumber=ISO7721FD, Operating Temperature Range="-55 to 125 C", Rating=Catalog
U4 U8 U12: library part CMP-0051578-2, "Single 2-Input Positive-AND Gate, DBV0005A (SOT-23-5)", Alternate Manufacturer="Texas Instruments", Alternate PartNumber=SN74AHC1G08DBVT, F @ Nom Voltage(Max)(Mhz)=75, Generic Part Number=SN74AHC1G08, ICC @ Nom Voltage(Max)(mA)=0.01, Operating Temperature Range(C)="-55 to 125", Rating=Catalog, tpd @ Nom Voltage(Max)(ns)=12.3,7.9, Voltage(Nom)(V)=3.3,5
U9: library part CMP-0051219-1, "Single 3-Input Positive-AND Gate, DBV0006A, LARGE T&R", F @ Nom Voltage(Max)(Mhz)=150, Generic Part Number=SN74LVC1G11, ICC @ Nom Voltage(Max)(mA)=0.01, Manufacturer="Texas Instruments", Operating Temperature Range(C)="-40 to 125,-40 to 85", Rating=Catalog, tpd @ Nom Voltage(Max)(ns)=20,7.8,6.2,4.6, Voltage(Nom)(V)=1.8,2.5,3.3,5
U10: library part CMP-0037130-1, "LDO with 4.7 to 15 V Input and 3.3 V Output, 0 to 125 degC, 8-Pin SON (DRJ), Green (RoHS & no Sb/Br)", Manufacturer="Texas Instruments"
U15 U16 U17 U18 U19 U20: library part CMP-0033071-1, "Adjustable Precision Shunt Regulator, 34 ppm / degC, 100 mA, 0 to 70 degC, 3-pin SOT-23 (DBZ), Green (RoHS & no Sb/Br)", Manufacturer="Texas Instruments", Rating=Catalog, Temp Coeff(Max)(ppm/ degree C)=92, Temp Coeff(Typ)(ppm/ degree C)=34
ZZ1: library part CMP-0003616-3
ZZ2: library part CMP-0077236-1
ZZ3: library part CMP-0077237-1
ZZ4: library part CMP-0077238-1

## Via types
v1: diameter 0.508, hole 0.254, Top Layer to Bottom Layer, 248 vias
v2: diameter 0.5, hole 0.2, Top Layer to Bottom Layer, 5 vias

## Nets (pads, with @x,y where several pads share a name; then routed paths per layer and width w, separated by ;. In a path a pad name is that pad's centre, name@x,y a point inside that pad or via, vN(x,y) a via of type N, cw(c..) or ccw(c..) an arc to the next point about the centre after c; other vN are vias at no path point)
3V3: C3.2 C9.1 C10.2 C14.2 C20.1 C21.2 C25.1 C30.2 C31.1 C36.2 C50.1 C53.2 R22.2 U2.1 U4.5 U5.1 U6.1 U8.5 U9.5 U10.5 U10.6 U10.7 U10.9 U11.1 U12.5 U13.1 U14.1 | length 23.1
  Top Layer w0.254: C36.2@13.5,33 13.5,33.864 v1(13.538,33.902) ; C36.2@13.538,33.038 13.671,32.905 U11.1@15.15,32.905 ; C9.1@36.233,39.719 35.982,39.467 U4.5@35.982,38.097 36.037,38.041 v1(36.639,38.041) ; v1(37.948,33.979) 37.948,33.089 C3.2@37.859,33 39.355,33 U2.1@39.45,32.905 ; U9.5@44.348,41.653 44.348,41.046 44.623,40.772 46.074,40.772 C25.1@46.914,41.611 ; v1(48.87,40.481) 48.895,40.456 R22.2@50.279,40.456 ; v1(60.731,37.738) 60.731,38.656 U8.5@60.75,38.675 60.75,40.131 C20.1@61.024,40.405 ; v1(62.484,33.902) 62.484,33.14 C14.2@62.344,33 63.855,33 U6.1@63.95,32.905
  Top Layer w0.381: U12.5@11.65,38.675 11.65,39.85 C50.1@11.9,40.1 11.9,41.161 v1(11.887,41.173) ; C25.1@46.914,41.611 v1(47.822,41.611)
  Bottom Layer w0.254: C31.1@78.181,43.478 78.181,42.468 v1(78.527,42.122)
  other v1: 38.933,14.903 39.497,14.903 14.5,15.1 15.1,15.1 63.068,15.132 63.627,15.132
  other v2: 76.911,38.647 76.061,39.897 76.911,39.897 77.761,39.897 76.911,41.147
5V: C28.1 C29.2 D1.1 J1.6 J1.8 U10.2 U10.3 U10.4 | length 36.5
  L3 w0.508: 35.89,44.443 66.573,44.443 67.615,43.402 v1(67.615,39.04)
  other v1: 74.27,39.059 74.27,39.821
5V_H_U: C26.1 C34.1 J3.6 R28.2 R29.2 U11.8 U15.1 | length 9
  Top Layer w0.254: U11.8@20.65,32.905 20.65,33.597 v1(20.752,33.699) ; v1(23.4,28.1) 23.6,28.3 U15.1@23.6,28.915 ; v1(24.863,26.215) 24.863,25.537 ccw(c25,25.537) R29.2@25,25.4 25.47,24.93 R28.2@26.518,24.93
  Bottom Layer w0.254: v1(20.752,33.699) 21.351,33.1 C34.1@22.4,33.1 ; C26.1@22.3,28.6 22.9,28.6 v1(23.4,28.1) 23.795,28.1 J3.6@24.525,28.83
5V_H_V: C4.1 C37.1 J6.6 R5.2 R6.2 U2.8 U17.1 | length 9.1
  Top Layer w0.254: v1(44.907,33.572) 44.907,32.948 ccw(c44.95,32.948) U2.8@44.95,32.905 ; v1(47.6,28.092) 47.9,28.393 U17.1@47.9,28.915 ; v1(49.327,26.215) 49.241,26.129 R6.2@49.241,25.298 50.013,25.298 50.147,25.164 R5.2@50.876,25.164
  Bottom Layer w0.254: v1(44.907,33.572) 45.379,33.1 C4.1@46.673,33.1 ; C37.1@46.482,28.638 47.028,28.092 v1(47.6,28.092) 48.087,28.092 J6.6@48.825,28.83
5V_H_W: C15.1 C39.1 J9.6 R12.2 R13.2 U6.8 U19.1 | length 8.9
  Top Layer w0.254: v1(69.444,33.648) 69.444,32.911 U6.8@69.45,32.905 ; v1(72.009,28.092) 72.009,28.718 U19.1@72.155,28.865 ; v1(73.863,26.01) 73.854,26 R13.2@73.854,25.171 73.968,25.057 R12.2@75.438,25.057
  Bottom Layer w0.254: v1(69.444,33.648) 69.992,33.1 C15.1@71.158,33.1 ; C39.1@70.891,28.461 71.641,28.461 v1(72.009,28.092) 72.747,28.83 J9.6@73.325,28.83
5V_L_U: C27.1 C52.1 J12.6 R1.2 R2.2 U13.8 U16.1 | length 8.6
  Top Layer w0.254: U13.8@20.65,14.105 20.9,14.355 v1(20.9,14.9) ; U16.1@23.3,10.35 23.3,9.415 v1(23.444,9.271) ; R2.2@26.6,7.1 26.8,7.3 v1(26.8,8.3) 27.073,8.573 R1.2@27.711,8.573
  Bottom Layer w0.254: v1(20.9,14.9) 21.5,14.3 C52.1@22.4,14.3 ; C27.1@22.575,9.8 23.104,9.271 v1(23.444,9.271) 23.766,9.271 J12.6@24.525,10.03
5V_L_V: C11.1 C38.1 J13.6 R35.2 R36.2 U5.8 U18.1 | length 8.7
  Top Layer w0.254: U5.8@44.95,14.105 45.161,14.316 v1(45.161,14.878) ; U18.1@47.517,10.17 cw(c47.517,10.139) 47.549,10.139 v1(47.549,9.322) ; R36.2@50.511,6.528 50.511,7.408 51.092,7.988 R35.2@51.892,7.988
  Bottom Layer w0.254: v1(45.161,14.878) 45.739,14.3 C11.1@46.774,14.3 ; C38.1@46.736,9.969 47.384,9.322 v1(47.549,9.322) 48.117,9.322 J13.6@48.825,10.03
  other v1: 50.825,7.722
5V_L_W: C22.1 C40.1 J14.6 R40.2 R41.2 U14.8 U20.1 | length 9
  Top Layer w0.254: U14.8@69.45,14.105 69.45,14.706 cw(c69.494,14.706) v1(69.494,14.751) ; v1(71.831,9.703) U20.1@71.831,10.393 ; v1(73.355,8.179) 73.358,8.176 73.358,7.582 R41.2@73.777,7.163 74.524,7.163 74.765,7.404 R40.2@75.59,7.404
  Bottom Layer w0.254: v1(69.494,14.751) 69.945,14.3 C22.1@71.2,14.3 ; C40.1@70.942,10.02 71.514,10.02 v1(71.831,9.703) 72.158,10.03 J14.6@73.325,10.03
12V: D4.2 D8.2 D11.2 J12.5 J13.5 J14.5 J16.2 R1.1 R35.1 R40.1 | length 109.2
  Top Layer w0.5: v1(75.54,10.052) 75.54,9.055 R40.1@75.59,9.004
  Top Layer w0.508: v1(26.594,10.077) 27.616,10.077 R1.1@27.711,10.173 ; v1(50.8,9.95) 51.162,9.588 R35.1@51.892,9.588
  L3 w0.508: J16.2@1.9,22.63 1.9,20.147 4.835,17.212 4.835,3.365 6.5,1.7 26.822,1.7 ; 27.381,7.112 27.381,2.259 ; 72.1,8.071 65.729,1.7 27.94,1.7 ; 26.822,1.7 27.381,2.259 ; 26.822,1.7 27.407,1.7 ; 27.381,2.259 27.407,2.233 ; 27.407,1.7 27.407,2.233 ; 27.407,1.7 27.94,1.7 ; 27.407,2.233 27.94,1.7
  Bottom Layer w0.254: D4.2@26.762,14.4 D4.2@26.9,14.263 ; J12.5@28.028,10.077 J12.5@28.075,10.03
  Bottom Layer w0.5: D4.2@26.716,14.446 D4.2@26.762,14.4 ; v1(50.133,14.395) 51.137,14.395 D8.2@51.2,14.333 ; v1(50.8,9.95) 50.88,10.03 J13.5@52.375,10.03 ; v1(74.701,14.446) 75.586,14.446 D11.2@75.7,14.332 ; v1(75.54,10.052) 76.853,10.052 J14.5@76.875,10.03
  Bottom Layer w0.508: v1(25.883,14.446) D4.2@26.716,14.446 ; v1(26.594,10.077) J12.5@28.028,10.077
12V_T_U: C32.1 J3.5 R26.2 R28.1 | length 10
  Top Layer w0.4: R28.1@26.518,26.53 27.8,26.53 27.8,26.6 ; v1(26.594,28.873) 27.027,28.873 27.8,28.1 27.8,26.6 ; R26.2@28.296,24.828 28.296,26.104 27.8,26.6
  Bottom Layer w0.4: v1(26.594,28.873) 26.637,28.83 J3.5@28.075,28.83 cw(c28.075,28.789) 28.116,28.789 C32.1@28.116,26.7
12V_T_V: C33.1 J6.5 R5.1 R7.2 | length 10.2
  Top Layer w0.381: R5.1@50.927,26.53 51.943,26.53 ; v1(50.978,28.772) 51.975,28.772 52.476,28.27 52.476,27.064 51.943,26.53 ; R7.2@52.578,24.803 52.578,25.895 51.943,26.53
  Bottom Layer w0.254: v1(50.978,28.772) 52.317,28.772 J6.5@52.375,28.83 52.585,28.62 C33.1@52.585,26.827
12V_T_W: C35.1 J9.5 R12.1 R14.2 | length 10.4
  Top Layer w0.254: R12.1@75.438,26.657 76.721,26.657 ; v1(75.463,28.772) 76.308,28.772 77.114,27.965 77.114,27.051 76.721,26.657 ; R14.2@77.191,24.752 77.191,26.187 76.721,26.657
  Bottom Layer w0.254: v1(75.463,28.772) 76.817,28.772 77.147,28.442 C35.1@77.147,26.721
Bot_FET_U: J1.4 R31.1 | length 57.5
  Top Layer w0.254: R31.1@11.9,10 10.819,11.081 10.819,27.732 9.83,28.721 9.83,42.223 11.187,43.58 30.742,43.58 31.28,44.118 32.253,44.118 J1.4@33.122,43.25
Bot_FET_V: J1.3 R8.1 | length 33.4
  Top Layer w0.254: J1.3@33.122,41.98 34.087,41.014 34.087,20.382 35.124,19.346 35.124,13.673 35.213,13.583 35.213,10.97 R8.1@36.259,9.925
Bot_FET_W: J1.13 R15.1 | length 53.5
  Top Layer w0.254: J1.13@39.472,41.98 41.039,41.98 42.131,43.072 58.517,43.072 58.847,42.742 58.847,11.872 R15.1@60.719,10
FAULT_H_U: J3.1 R25.2 | length 5.4
  Top Layer w0.254: R25.2@24,33.6 26.319,33.6 v1(27.483,32.436)
  Bottom Layer w0.254: v1(27.483,32.436) 27.483,31.674 27.787,31.37 J3.1@28.075,31.37
FAULT_H_V: J6.1 R4.2 | length 5.5
  Top Layer w0.254: R4.2@48.273,33.6 50.869,33.6 v1(51.892,32.577)
  Bottom Layer w0.254: v1(51.892,32.577) 52.375,32.094 J6.1@52.375,31.37
FAULT_H_W: J9.1 R11.2 | length 5.2
  Top Layer w0.254: R11.2@72.758,33.6 73.378,33.6 74.879,32.099 v1(76.403,32.099)
  Bottom Layer w0.254: v1(76.403,32.099) 76.403,31.842 J9.1@76.875,31.37
FAULT_L_U: J12.1 R32.2 | length 5.4
  Top Layer w0.254: R32.2@24.1,15.1 24.289,15.1 26.06,13.328 v1(27.432,13.328)
  Bottom Layer w0.254: v1(27.432,13.328) 27.895,13.328 28.075,13.148 J12.1@28.075,12.57
FAULT_L_V: J13.1 R9.2 | length 5.5
  Top Layer w0.254: R9.2@48.298,15.1 50.07,13.328 51.664,13.328 v1(51.689,13.354)
  Bottom Layer w0.254: v1(51.689,13.354) 52.137,13.354 52.375,13.116 J13.1@52.375,12.57
FAULT_L_W: J14.1 R16.2 | length 5.1
  Top Layer w0.254: R16.2@72.8,15.1 74.572,13.328 v1(75.717,13.328)
  Bottom Layer w0.254: v1(75.717,13.328) 76.117,13.328 J14.1@76.875,12.57
FLT_L_U: U12.1 U13.2 | length 27.5
  Top Layer w0.254: U12.1@11.65,35.925 v1(11.65,37.05) ; v1(13.9,12.9) 15.085,12.9 cw(c15.085,12.835) U13.2@15.15,12.835
  L3 w0.254: v1(11.65,37.05) 11.65,32.412 13.386,30.677 13.386,13.414 v1(13.9,12.9)
FLT_L_V: U4.1 U5.2 | length 26.8
  Top Layer w0.254: U4.1@35.982,35.347 v1(35.982,36.472) ; v1(38.329,12.871) 39.414,12.871 U5.2@39.45,12.835
  L3 w0.254: v1(35.982,36.472) 36.805,35.649 36.805,18.847 36.832,18.82 36.832,18.815 38.298,17.348 38.298,12.902 v1(38.329,12.871)
FLT_L_W: U8.1 U14.2 | length 27.3
  Top Layer w0.254: v1(60.731,36.95) 60.731,35.944 U8.1@60.75,35.925 ; v1(62.611,12.846) 63.939,12.846 U14.2@63.95,12.835
  L3 w0.254: v1(60.731,36.95) 60.731,33.013 61.265,32.479 61.265,18.826 62.069,18.022 62.069,13.388 v1(62.611,12.846)
FLT_T_U: U11.2 U12.2 | length 8.7
  Top Layer w0.254: U12.2@12.6,35.925 v1(12.6,37.05) ; v1(14,31.7) ccw(c14.065,31.7) 14.065,31.635 U11.2@15.15,31.635
  L3 w0.254: v1(12.6,37.05) 12.6,32.25 13.15,31.7 v1(14,31.7)
FLT_T_V: U2.2 U4.2 | length 7.8
  Top Layer w0.254: v1(36.906,36.472) 36.906,35.372 U4.2@36.932,35.347 ; v1(38.151,31.616) 39.431,31.616 U2.2@39.45,31.635
  L3 w0.254: v1(36.906,36.472) 37.313,36.065 37.313,32.505 38.151,31.667 v1(38.151,31.616)
FLT_T_W: U6.2 U8.2 | length 7.9
  Top Layer w0.254: U8.2@61.7,35.925 61.773,35.998 v1(61.773,36.95) ; v1(62.789,31.642) 62.796,31.635 U6.2@63.95,31.635
  L3 w0.254: v1(61.773,36.95) 61.773,32.658 v1(62.789,31.642)
"GaN Fault": J1.11 R27.2 U9.4 | length 8.8
  Top Layer w0.254: J1.11@38.202,41.98 39.267,40.915 40.693,40.915 42.342,42.564 44.746,42.564 45.298,42.012 U9.4@45.298,41.653
"GaN Fault U": U9.6 U12.4 | length 31.2
  Top Layer w0.254: U12.4@13.55,38.675 14.323,38.675 v1(14.326,38.678) ; v1(42.599,41.827) 43.224,41.827 U9.6@43.398,41.653
  L3 w0.254: v1(14.326,38.678) 14.802,38.678 16.986,40.862 41.504,40.862 42.469,41.827 v1(42.599,41.827)
"GaN Fault V": U4.4 U9.1 | length 6
  Top Layer w0.254: U4.4@37.882,38.097 39.602,38.097 40.013,38.508 42.724,38.508 U9.1@43.449,39.233
"GaN Fault W": U8.4 U9.3 | length 17.7
  Top Layer w0.254: U9.3@45.298,38.903 45.454,39.059 v1(46.152,39.059) ; v1(61.824,38.678) 61.826,38.675 U8.4@62.65,38.675
  L3 w0.254: v1(46.152,39.059) 61.443,39.059 v1(61.824,38.678) v1@61.747,38.601
GND: C3.1 C5.2 C9.2 C10.1 C12.2 C14.1 C16.2 C20.2 C21.1 C23.2 C25.2 C28.2 C29.1 C30.1 C31.2 C36.1 C45.2 C50.2 C53.1 C56.2 D2.2 J1.9 J1.10 J2.1 R27.1 U2.4 U4.3 U5.4 U6.4 U8.3 U9.2 U10.1 U11.4 U12.3 U13.4 U14.4 | length 37.1
  Top Layer w0.254: C36.1@11.9,33 11.9,31.634 11.633,31.367 C45.2@12.4,30.6 ; v1(12.37,12.49) 12.37,11.53 C56.2@12.4,11.5 ; v1(13.5,37.05) 13.5,35.975 ccw(c13.55,35.975) U12.3@13.55,35.925 ; C50.2@13.5,40.1 13.5,41.179 v1(13.513,41.192) ; v1(15.062,9.595) 15.062,10.207 U13.4@15.15,10.295 ; v1(15.126,28.452) 15.126,29.071 U11.4@15.15,29.095 ; C3.1@36.259,33 36.068,32.809 v1(36.068,31.693) 36.068,31.232 C5.2@36.7,30.6 ; C12.2@36.713,11.398 36.713,12.246 cw(c36.779,12.246) v1(36.779,12.312) ; C9.2@37.833,39.719 37.909,39.643 v1(38.786,39.643) 40.757,39.643 R27.1@40.8,39.6 ; v1(37.846,36.472) 37.846,35.382 U4.3@37.882,35.347 ; v1(39.141,28.391) 39.141,28.786 U2.4@39.45,29.095 ; v1(39.345,9.544) 39.345,10.19 U5.4@39.45,10.295 ; U9.2@44.348,38.903 44.348,39.827 44.532,40.011 C25.2@46.914,40.011 ; C14.1@60.744,33 60.579,32.835 v1(60.579,31.566) 60.579,31.221 C16.2@61.2,30.6 ; C23.2@61.198,11.5 61.198,12.236 v1(61.214,12.236) ; C20.2@62.624,40.405 63.576,40.405 v1(63.627,40.354) ; U8.3@62.65,35.925 62.662,35.937 v1(62.662,36.95) ; v1(63.602,28.365) 63.602,28.747 U6.4@63.95,29.095 ; v1(63.754,9.595) 63.754,10.099 U14.4@63.95,10.295 ; v1(74.066,41.885) 74.066,41.529 74.499,41.097 U10.1@75.011,41.097
  Top Layer w0.3: D2.2@54.954,40.456 56.109,40.456 v1(56.159,40.405)
  Top Layer w0.381: C25.2@46.914,40.011 v1(47.822,40.011) ; v1(75.006,43.935) 75.108,43.834 C30.1@76.175,43.834
  Bottom Layer w0.508: C29.1@71.171,41.446 71.171,43.101 J2.1@71.97,43.9 ; C28.2@73.127,41.338 73.127,43.104 73.152,43.129
  other v1: 60.884,15.03 36.322,15.056 12.274,15.084 12.263,15.629 11.587,31.349
HVBUS: J4.1 J4.2 J4.3 J4.4 J4.5 J4.6 J5.2
HVBUS_RTN: C11.2 C13.2 C22.2 C24.2 C27.2 C38.2 C40.2 C52.2 C57.2 J5.1 J11.1 J11.2 J11.3 J11.4 J11.5 J11.6 J12.3 J12.4 J13.3 J13.4 J14.3 J14.4 J16.1 R33.1 R37.1 R43.1 U5.5 U13.5 U14.5 U16.3 U18.3 U20.3 | length 118.5
  Top Layer w0.254: v1(20.625,9.474) 20.65,9.499 U13.5@20.65,10.295 ; C57.2@23.612,13.575 v1(24.816,13.575) 24.975,13.575 v1@25,13.6 ; v1(25.7,8.3) U16.3@25.7,9.4 ; U5.5@44.95,10.295 44.958,10.287 v1(44.958,9.518) ; v1(45.415,6.528) 45.441,6.553 R37.1@46.568,6.553 ; C13.2@47.793,13.575 47.887,13.481 v1(48.87,13.481) ; v1(49.903,8.252) 49.903,9.206 U18.3@49.917,9.22 ; U14.5@69.45,10.295 69.45,9.62 v1(69.596,9.474) ; v1(69.672,8.103) 69.672,7.274 R43.1@69.783,7.163 ; C24.2@72.304,13.6 73.16,13.6 v1(73.279,13.481) ; U20.3@74.174,9.5 74.193,9.48 v1(74.193,8.687)
  Top Layer w0.508: v1(21.432,7.356) 21.687,7.1 R33.1@22.6,7.1
  L3 w0.508: J5.1@2.6,39.875 6.553,35.922 6.553,31.394 1.9,26.741 J16.1@1.9,25.17 5.597,21.473 5.597,3.68 6.816,2.462 20.162,2.462 20.8,3.1 20.8,4.67
  Bottom Layer w0.254: C52.2@24,14.3 C52.2@24.3,14.3 ; C22.2@72.8,14.3 73.279,13.821 v1(73.279,13.481)
  Bottom Layer w0.508: v1(25.432,4.956) 27.448,4.956 28.6,3.804 65.704,3.804 69.4,7.5
  other v1: 22.191,4.937 22.841,4.937 23.491,4.937 24.132,4.956 24.782,4.956 20.144,5.432 20.782,5.432 21.444,5.432 22.216,5.546 22.866,5.546 23.516,5.546 24.132,5.556 24.782,5.556 25.432,5.556 20.144,6.082 20.782,6.082 21.444,6.082 20.144,6.732 20.782,6.732 21.444,6.732 20.132,7.356 20.782,7.356 20.132,7.956 20.782,7.956 21.432,7.956
IN_H_U: J3.2 R17.2 | length 3.9
  Top Layer w0.254: R17.2@24,30.6 25.552,32.152 v1(25.552,32.258)
  Bottom Layer w0.254: J3.2@24.525,31.37 25.071,31.37 25.552,31.852 v1(25.552,32.258)
IN_H_V: J6.2 R19.2 | length 3.9
  Top Layer w0.254: R19.2@48.273,30.6 49.453,30.6 v1(50.292,31.439)
  Bottom Layer w0.254: J6.2@48.825,31.37 48.894,31.439 v1(50.292,31.439)
IN_H_W: J9.2 R21.2 | length 4
  Top Layer w0.254: R21.2@72.8,30.6 74.091,30.6 v1(74.879,31.388)
  Bottom Layer w0.254: J9.2@73.325,31.37 74.861,31.37 v1(74.879,31.388)
IN_L_U: J12.2 R18.2 | length 3.3
  Top Layer w0.254: R18.2@24.4,12.1 25.5,12.1 v1(26,12.6)
  Bottom Layer w0.254: J12.2@24.525,12.57 25.97,12.57 v1(26,12.6)
IN_L_V: J13.2 R20.2 | length 3.7
  Top Layer w0.254: R20.2@48.3,12.1 49.826,12.1 v1(50.292,12.566)
  Bottom Layer w0.254: J13.2@48.825,12.57 50.288,12.57 v1(50.292,12.566)
IN_L_W: J14.2 R23.2 | length 3.6
  Top Layer w0.254: R23.2@72.8,12.1 74.311,12.1 v1(74.778,12.566)
  Bottom Layer w0.254: J14.2@73.325,12.57 74.774,12.57 v1(74.778,12.566)
NC1: J1.2 | length 0.3
  Top Layer w0.254: J1.2@31.674,43.072 J1.2@31.852,43.25
NC2: J1.14
NC3: J1.5 | length 0.3
  Top Layer w0.254: J1.5@34.392,41.98 J1.5@34.595,41.776
NC4: U10.8
NetC5_1: C5.1 R3.2 U2.3 | length 3.2
  Top Layer w0.254: R3.2@37.8,29.1 37.9,29.2 C5.1@37.9,30.6 38.304,30.6 38.539,30.365 U2.3@39.45,30.365
NetC6_1: C6.1 R4.1 U2.7 | length 3.4
  Top Layer w0.254: U2.7@44.95,31.635 46.103,31.635 C6.1@46.568,32.1 46.673,32.205 R4.1@46.673,33.6
NetC12_1: C12.1 R8.2 U5.3 | length 3.1
  Top Layer w0.254: R8.2@37.859,9.925 37.913,9.979 C12.1@37.913,11.398 38.08,11.565 U5.3@39.45,11.565
NetC13_1: C13.1 R9.1 U5.7 | length 3.5
  Top Layer w0.254: U5.7@44.95,12.835 45.853,12.835 C13.1@46.593,13.575 46.698,13.68 R9.1@46.698,15.1
NetC16_1: C16.1 R10.2 U6.3 | length 3.2
  Top Layer w0.254: R10.2@62.319,29.1 62.4,29.181 C16.1@62.4,30.6 63.17,30.6 63.405,30.365 U6.3@63.95,30.365
NetC17_1: C17.1 R11.1 U6.7 | length 3.4
  Top Layer w0.254: U6.7@69.45,31.635 70.614,31.635 C17.1@71.079,32.1 71.158,32.179 R11.1@71.158,33.6
NetC23_1: C23.1 R15.2 U14.3 | length 3.1
  Top Layer w0.254: R15.2@62.319,10 62.398,10.079 C23.1@62.398,11.5 63.885,11.5 U14.3@63.95,11.565
NetC24_1: C24.1 R16.1 U14.7 | length 3.5
  Top Layer w0.254: U14.7@69.45,12.835 70.339,12.835 C24.1@71.104,13.6 71.2,13.696 R16.1@71.2,15.1
NetC45_1: C45.1 R24.2 U11.3 | length 3.2
  Top Layer w0.254: R24.2@13.5,29.1 13.6,29.2 C45.1@13.6,30.6 14.05,30.6 14.285,30.365 U11.3@15.15,30.365
NetC47_1: C47.1 R25.1 U11.7 | length 3.4
  Top Layer w0.254: U11.7@20.65,31.635 21.835,31.635 C47.1@22.3,32.1 22.4,32.2 R25.1@22.4,33.575
NetC56_1: C56.1 R31.2 U13.3 | length 3.1
  Top Layer w0.254: R31.2@13.5,10 13.6,10.1 C56.1@13.6,11.5 15.085,11.5 U13.3@15.15,11.565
